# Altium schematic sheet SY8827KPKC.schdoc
size 127 x 101 mm
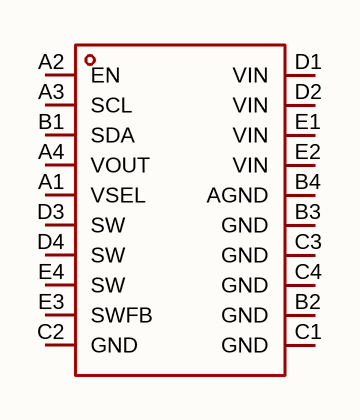
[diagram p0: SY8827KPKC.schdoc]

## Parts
U?  sy8827kpkc  [CSP-20_L2.0-W1.6-R4-C5-P0.40-BL]  (value not drawn)

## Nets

Not connected (* = marked no-connect by the designer): U? A1(VSEL) A2(EN) A3(SCL) A4(VOUT) B1(SDA) B2(GND) B3(GND) B4(AGND) C1(GND) C2(GND) C3(GND) C4(GND) D1(VIN) D2(VIN) D3(SW) D4(SW) E1(VIN) E2(VIN) E3(SWFB) E4(SW)

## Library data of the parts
U? = sy8827kpkc: 功能类型:降压型;工作电压:2.6V~5.5V;输出电压:712.5mV~1.5V;输出电流:6A;输出类型:可调;; Manufacturer: Silergy(矽力杰); AddInBom: yes; ModelId: 4f0ee11102de4cc9a118061f98604006; ModelTransform: 78.74,62.992,0,0,0,0,0,0,0; Function: 降压型; Output Current: 6A; Frequency - Switching: 2.4MHz; Synchronous Rectifier: 是; Number of Outputs: 1; Topology: 降压式; Quiescent Current: 75uA; Switch tube (built-in/external): 内置; Output Type: 可调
